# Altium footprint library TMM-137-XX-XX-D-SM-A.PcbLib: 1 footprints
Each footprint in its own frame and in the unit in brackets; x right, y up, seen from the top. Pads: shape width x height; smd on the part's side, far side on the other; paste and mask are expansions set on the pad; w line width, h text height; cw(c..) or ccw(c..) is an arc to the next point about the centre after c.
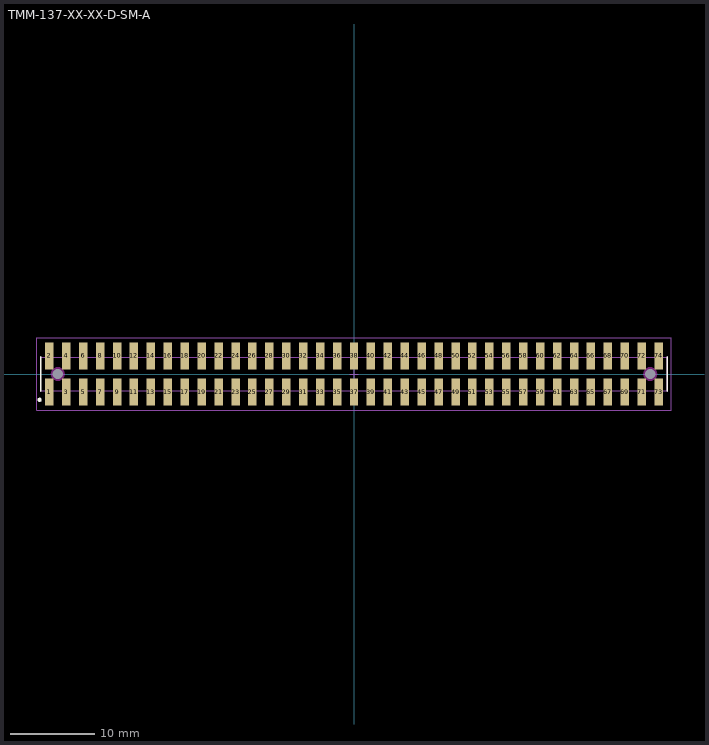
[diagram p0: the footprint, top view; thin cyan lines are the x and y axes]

## TMM-137-XX-XX-D-SM-A [mm] "2.00mm pitch, 74 pin, terminal strip; double row, w/alignment pins, SMT"
height 2.77
pads (76):
  rect 1x3.2 smd mask+0: 1(-36,-2.15) 2(-36,2.15) 3(-34,-2.15) 4(-34,2.15) 5(-32,-2.15) 6(-32,2.15) 7(-30,-2.15) 8(-30,2.15) 9(-28,-2.15) 10(-28,2.15) 11(-26,-2.15) 12(-26,2.15) 13(-24,-2.15) 14(-24,2.15) 15(-22,-2.15) 16(-22,2.15) 17(-20,-2.15) 18(-20,2.15) 19(-18,-2.15) 20(-18,2.15) 21(-16,-2.15) 22(-16,2.15) 23(-14,-2.15) 24(-14,2.15) 25(-12,-2.15) 26(-12,2.15) 27(-10,-2.15) 28(-10,2.15) 29(-8,-2.15) 30(-8,2.15) 31(-6,-2.15) 32(-6,2.15) 33(-4,-2.15) 34(-4,2.15) 35(-2,-2.15) 36(-2,2.15) 37(0,-2.15) 38(0,2.15) 39(2,-2.15) 40(2,2.15) 41(4,-2.15) 42(4,2.15) 43(6,-2.15) 44(6,2.15) 45(8,-2.15) 46(8,2.15) 47(10,-2.15) 48(10,2.15) 49(12,-2.15) 50(12,2.15) 51(14,-2.15) 52(14,2.15) 53(16,-2.15) 54(16,2.15) 55(18,-2.15) 56(18,2.15) 57(20,-2.15) 58(20,2.15) 59(22,-2.15) 60(22,2.15) 61(24,-2.15) 62(24,2.15) 63(26,-2.15) 64(26,2.15) 65(28,-2.15) 66(28,2.15) 67(30,-2.15) 68(30,2.15) 69(32,-2.15) 70(32,2.15) 71(34,-2.15) 72(34,2.15) 73(36,-2.15) 74(36,2.15)
  round 1 hole 1.2 unplated mask+0: 75(-35,0) 76(35,0)
Top Overlay:
  circle w0.25: c-37.15,-3.05 r0.125
  lines w0.2: -37,-2 -37,2 ; 37,-2 37,2
Keep-Out Layer:
  pour cut-out: 35.807,0 35.779,0.209 35.699,0.403 35.57,0.571 35.403,0.699 35.209,0.779 35,0.807 34.791,0.779 34.596,0.699 34.429,0.571 34.301,0.403 34.22,0.209 34.193,0 34.22,-0.209 34.301,-0.403 34.429,-0.571 34.596,-0.699 34.791,-0.779 35,-0.807 35.209,-0.779 35.403,-0.699 35.57,-0.571 35.699,-0.403 35.779,-0.209
  pour cut-out: -34.193,0 -34.22,0.209 -34.301,0.403 -34.429,0.571 -34.596,0.699 -34.791,0.779 -35,0.807 -35.209,0.779 -35.403,0.699 -35.57,0.571 -35.699,0.403 -35.779,0.209 -35.807,0 -35.779,-0.209 -35.699,-0.403 -35.57,-0.571 -35.403,-0.699 -35.209,-0.779 -35,-0.807 -34.791,-0.779 -34.596,-0.699 -34.429,-0.571 -34.301,-0.403 -34.22,-0.209
Mechanical 12:
  lines w0.001: -37,-2 -37,2 37,2 37,-2 -37,-2
Mechanical 13:
  lines w0.1: -37,-2 -37,2 37,2 37,-2 -37,-2
  text ".Designator" at 0,-0.127 h1.52
Mechanical 15:
  lines w0.05: -0.5,0 0.5,0 ; 0,-0.5 0,0.5 ; -37.5,-4.3 -37.5,4.3 37.5,4.3 37.5,-4.3 -37.5,-4.3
